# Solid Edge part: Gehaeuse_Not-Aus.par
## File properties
Author: Ferdi HM
Template: Din Metric Part.par
Last saved by: Ferdi
Revision: 13
Application: Solid Edge
Genauigkeit: 0,990
Username: Ferdi HM
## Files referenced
C:\Users\mucma\Desktop\Projektarbeit\Gehaeuse_Unterteil.par
D:\OneDrive\Dokumente\HM\6. (Fach-) Semester\Projektarbeit - Glasboilermaschine\Gehäuse Not-Aus\Gehaeuse_Not-Aus.par
use Not-Aus\Gehaeuse_Not-Aus.par
use_Not-Aus.asm
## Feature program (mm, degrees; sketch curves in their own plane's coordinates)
sketch for "unnamed Protrusion 1" #1 plane through (0, 0, 0) normal (0, 0, 1) x-axis (1, 0, 0)
  line (19.5, 30) -> (-19.5, 30)
  line (-19.5, 30) -> (-19.5, -30)
  line (-19.5, -30) -> (19.5, -30)
  line (19.5, -30) -> (19.5, 30)
sketch for "unnamed Protrusion 1" #2 plane through (0, 0, 0) normal (0, 0, 1) x-axis (1, 0, 0)
extrude "unnamed Protrusion 1" add finite 65 along +normal
sketch for "Extrusionsausprägung_2" plane through (0, 0, 65) normal (0, 0, 1) x-axis (1, 0, 0)
  line (-19.5, 30) -> (19.5, 30)
  line (19.5, 30) -> (19.5, -30)
  line (19.5, -30) -> (-19.5, -30)
  line (-19.5, -30) -> (-19.5, 30)
extrude "Extrusionsausprägung_2" add finite 2 along +normal
sketch for "Bohrung_1" plane through (0, 0, 67) normal (0, 0, 1) x-axis (1, 0, 0)
  hole centre (0, 0) bore radius 11
hole "Bohrung_1" diameter 22 through
sketch for "unnamed Cutout 1" plane through (0, -30, 33.5) normal (0, -1, 0) x-axis (1, 0, 0)
  line (4, -29.5) -> (4, -33.5)
  line (-4, -33.5) -> (4, -33.5)
  line (-4, -29.5) -> (-4, -33.5)
  dimension (linear) = 4
  dimension (linear) = 4
  dimension (linear) = 4
extrude "unnamed Cutout 1" cut through along -normal
sketch for "Extrusionsausprägung_6" #1 plane through (-11.75, 0, 0) normal (0, 0, -1) x-axis (0, -1, 0)
  line (-28, -2.25) -> (-20, -2.25)
  line (-20, -2.25) -> (-20, 5.75)
  line (-20, 5.75) -> (-28, 5.75)
  line (-28, 5.75) -> (-28, -2.25)
  dimension (linear) = 28
sketch for "Extrusionsausprägung_6" #2 plane through (-11.75, 0, 0) normal (0, 0, -1) x-axis (0, -1, 0)
  line (20, -2.25) -> (28, -2.25)
  line (28, -2.25) -> (28, 5.75)
  line (28, 5.75) -> (20, 5.75)
  line (20, 5.75) -> (20, -2.25)
sketch for "Extrusionsausprägung_6" #3 plane through (-11.75, 0, 0) normal (0, 0, -1) x-axis (0, -1, 0)
  line (-28, -29.25) -> (-20, -29.25)
  line (-20, -29.25) -> (-20, -21.25)
  line (-20, -21.25) -> (-28, -21.25)
  line (-28, -21.25) -> (-28, -29.25)
sketch for "Extrusionsausprägung_6" #4 plane through (-11.75, 0, 0) normal (0, 0, -1) x-axis (0, -1, 0)
  line (20, -29.25) -> (28, -29.25)
  line (28, -29.25) -> (28, -21.25)
  line (28, -21.25) -> (20, -21.25)
  line (20, -21.25) -> (20, -29.25)
extrude "Extrusionsausprägung_6" add finite 6 along -normal
sketch for "Bohrung_6" plane through (-11.75, 0, 0) normal (0, 0, -1) x-axis (0, -1, 0)
hole "Bohrung_6" diameter 3.3 through
sketch for "unnamed Hole 1" plane through (-11.75, 0, 0) normal (0, 0, -1) x-axis (0, -1, 0)
  hole centre (-24, 1.75) bore radius 1.65
hole "unnamed Hole 1" through
sketch for "unnamed Hole 2" plane through (-11.75, 0, 0) normal (0, 0, -1) x-axis (0, -1, 0)
  hole centre (24, 1.75) bore radius 1.65
hole "unnamed Hole 2" through
sketch for "unnamed Hole 3" plane through (-11.75, 0, 0) normal (0, 0, -1) x-axis (0, -1, 0)
  hole centre (24, -25.25) bore radius 1.65
hole "unnamed Hole 3" through
pattern "unnamed Pattern 1" of "Bohrung_6", "unnamed Hole 1", "unnamed Hole 2", "unnamed Hole 3"
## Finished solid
Body 1: solid body, 35 faces, 94 edges, 56 vertices.
  Faces by surface: plane 28, cylinder 7
  Edges by curve: line 80, circle 14
Bounding box of the edges (mm): 39.000 x 60.000 x 67.000, from (-19.5, -30, 0) to (19.5, 30, 67).
Cylindrical faces by radius (mm): R1.65 x4, R4 x2, R11 x1
Planar faces by outward normal: +x 6, +y 4, +z 5, -x 6, -y 4, -z 3
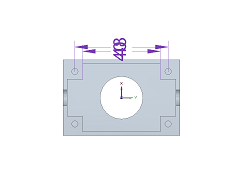
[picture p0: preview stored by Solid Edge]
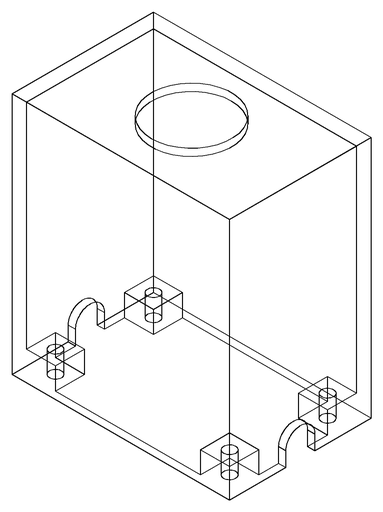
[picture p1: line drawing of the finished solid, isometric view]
